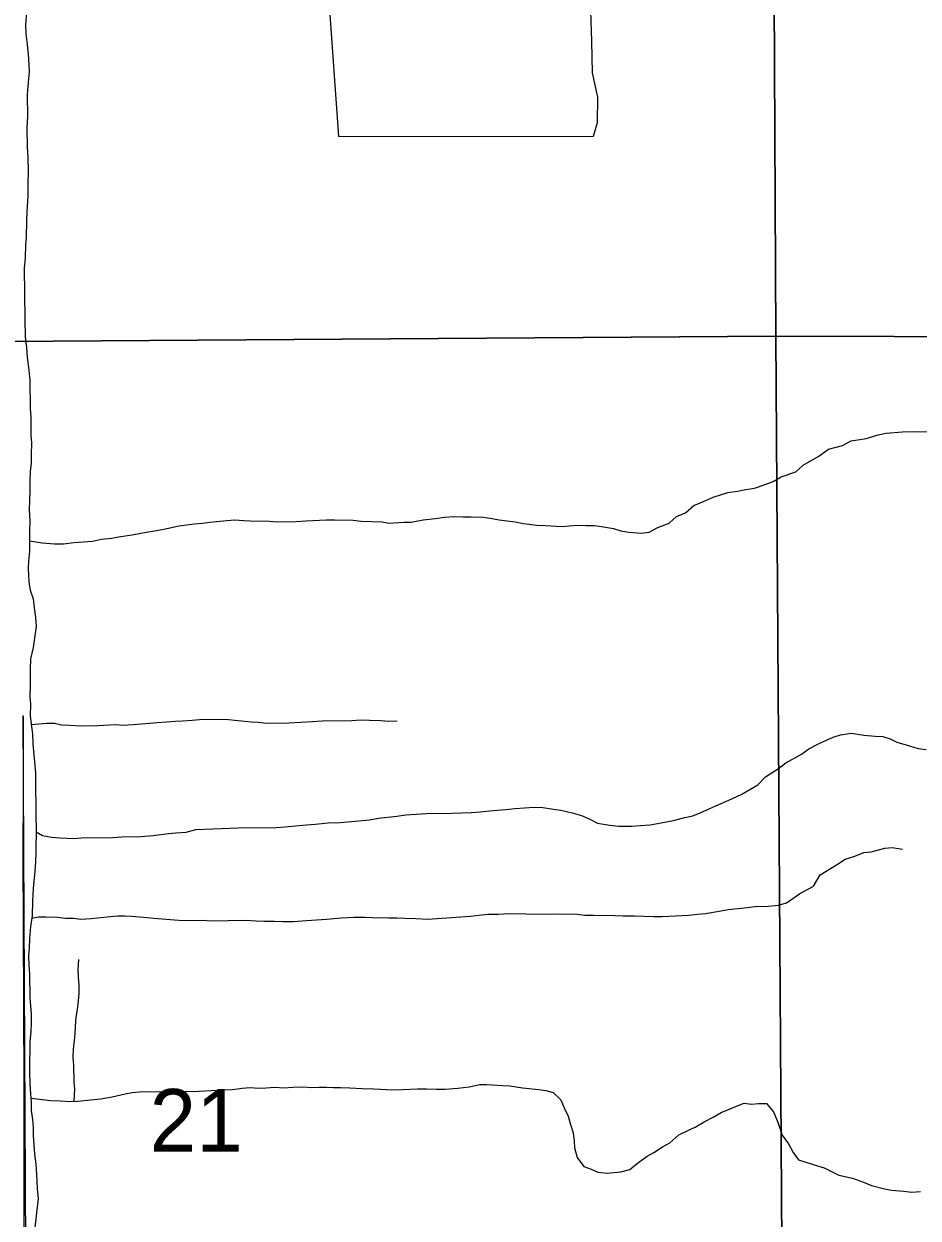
# Model space of a CAD drawing. Extents: x 0 to 34, y 0 to 22.
# Drawn here: x 19.767 to 20.365, y 11.016 to 11.815 of the extents above; entities that cross this region are included whole.
import ezdxf

# ---------------------------------------------------------------- set-up
doc = ezdxf.new("R2010")
doc.units = 0
for name, color, linetype in [('GM_X_Corporation', 7, 'Continuous'), ('GM_X_County_Road', 7, 'Continuous'), ('GM_X_Minor_Lake', 7, 'Continuous'), ('GM_X_Minor_River', 7, 'Continuous'), ('GM_X_Section', 7, 'Continuous'), ('GM_X_Section_Text', 7, 'Continuous')]:
    doc.layers.add(name, color=color, linetype=linetype)

msp = doc.modelspace()

# ---------------------------------------------------------------- linework, layer by layer
at = {"layer": 'GM_X_Corporation'}
msp.add_lwpolyline([(19.26385, 10.07977), (19.77404, 10.1041), (19.77373, 10.13544), (19.77365, 10.17896), (19.7732, 10.26602), (19.77132, 10.47124), (19.77058, 10.53033), (19.7704, 10.56452), (19.77, 10.59281), (19.7662, 11.35213)], dxfattribs=at)
at = {"layer": 'GM_X_County_Road'}
msp.add_lwpolyline([(19.77021, 10.59227), (19.77008, 10.62614), (19.76917, 10.71322), (19.76858, 10.77229), (19.76806, 10.82203), (19.76765, 10.85625), (19.76705, 10.92776), (19.76695, 10.97745), (19.7668, 11.02098), (19.76678, 11.10493), (19.76644, 11.21065), (19.76622, 11.25724), (19.76641, 11.3038), (19.76628, 11.32232), (19.76641, 11.35159)], dxfattribs=at)
at = {"layer": 'GM_X_Minor_Lake'}
for points in [[(19.97712, 11.73997), (20.14794, 11.74011), (20.15053, 11.74923), (20.15079, 11.7663), (20.14727, 11.78258), (20.14674, 11.80343), (20.14622, 11.82391), (20.142, 11.83222), (20.13629, 11.83635), (20.12909, 11.83668), (19.97081, 11.83094)], [(19.97081, 11.83094), (19.97712, 11.73997)]]:
    msp.add_lwpolyline(points, dxfattribs=at)
at = {"layer": 'GM_X_Minor_River'}
for points in [[(19.76846, 11.8231), (19.76781, 11.81474), (19.76789, 11.80866), (19.76874, 11.80145), (19.76958, 11.79501), (19.77005, 11.78818), (19.77012, 11.78324), (19.76945, 11.77601), (19.76879, 11.76803), (19.76899, 11.75322), (19.76871, 11.74562), (19.76887, 11.7327), (19.76934, 11.72587), (19.76946, 11.71637), (19.76919, 11.70801), (19.7693, 11.70004), (19.76867, 11.6894), (19.76837, 11.68369), (19.76813, 11.67229), (19.76782, 11.66735), (19.76755, 11.65861), (19.76688, 11.65176), (19.76732, 11.61758), (19.76748, 11.60543), (19.76833, 11.5986), (19.7688, 11.59177), (19.77005, 11.58343), (19.77052, 11.5766), (19.77076, 11.55761), (19.77121, 11.5523), (19.77137, 11.54015), (19.77183, 11.53445), (19.77154, 11.52685), (19.77162, 11.52116), (19.77093, 11.51545), (19.77063, 11.50937), (19.77071, 11.50291), (19.77042, 11.49645), (19.77013, 11.48961), (19.7706, 11.48278), (19.77031, 11.47518), (19.77048, 11.46226), (19.76981, 11.45542), (19.76949, 11.45048), (19.76999, 11.44174), (19.77082, 11.43606), (19.7728, 11.43038), (19.77363, 11.42432), (19.77448, 11.41787), (19.77494, 11.4118), (19.77284, 11.39772), (19.77104, 11.3901), (19.77075, 11.38288), (19.77088, 11.373), (19.77061, 11.36464), (19.77105, 11.35971), (19.77077, 11.35211), (19.77161, 11.34642), (19.77245, 11.33998), (19.77254, 11.33314), (19.77298, 11.32821), (19.77387, 11.31872), (19.77431, 11.31379)], [(19.77039, 11.4691), (19.77878, 11.46769), (19.78715, 11.46704), (19.79324, 11.46712), (19.80007, 11.46798), (19.81261, 11.4689), (19.81868, 11.47012), (19.82552, 11.47097), (19.83007, 11.47179), (19.83918, 11.47305), (19.84487, 11.47427), (19.85929, 11.47674), (19.86536, 11.47796), (19.87029, 11.47916), (19.88092, 11.48044), (19.88624, 11.4809), (19.89118, 11.48172), (19.90257, 11.48263), (19.90789, 11.48308), (19.9136, 11.48278), (19.91817, 11.48246), (19.93111, 11.48225), (19.93644, 11.48194), (19.94899, 11.48211), (19.95544, 11.48258), (19.96913, 11.48314), (19.97445, 11.48321), (19.98701, 11.483), (19.99234, 11.48231), (20.00642, 11.48173), (20.01099, 11.48103), (20.02088, 11.48155), (20.02582, 11.48161), (20.03379, 11.48324), (20.04214, 11.48411), (20.04822, 11.48495), (20.05468, 11.48541), (20.06077, 11.48512), (20.06609, 11.48519), (20.07408, 11.48491), (20.07865, 11.48421), (20.08475, 11.48315), (20.09542, 11.48178), (20.10114, 11.48072), (20.1099, 11.47969), (20.11561, 11.47939), (20.12703, 11.47878), (20.13159, 11.47922), (20.13729, 11.47968), (20.14299, 11.47937), (20.14832, 11.47944), (20.15327, 11.47875), (20.16128, 11.47733), (20.16624, 11.47588), (20.17158, 11.47481), (20.17996, 11.47416), (20.18527, 11.475), (20.19093, 11.47811), (20.19851, 11.48087), (20.20339, 11.48549), (20.20945, 11.48785), (20.21509, 11.49287), (20.2219, 11.49562), (20.22795, 11.49835), (20.23779, 11.50152), (20.24425, 11.50237), (20.24994, 11.50358), (20.25563, 11.50442), (20.26283, 11.5068), (20.26813, 11.50876), (20.27341, 11.51187), (20.28325, 11.51542), (20.28814, 11.51967), (20.29871, 11.52589), (20.30512, 11.53053), (20.3146, 11.53293), (20.32026, 11.53605), (20.33051, 11.5377), (20.33846, 11.54009), (20.34377, 11.5413), (20.35479, 11.54221), (20.36278, 11.54231), (20.37381, 11.54208)], [(19.77164, 11.34616), (19.78187, 11.34694), (19.78719, 11.34701), (19.79177, 11.34593), (19.79748, 11.34563), (19.80471, 11.34534), (19.81612, 11.34549), (19.82828, 11.34604), (19.83285, 11.34572), (19.83969, 11.34619), (19.85071, 11.34709), (19.85603, 11.34754), (19.86819, 11.34847), (19.87275, 11.34852), (19.87921, 11.34899), (19.88415, 11.34944), (19.90126, 11.34966), (19.91878, 11.348), (19.92335, 11.34768), (19.92906, 11.347), (19.94427, 11.3472), (19.95985, 11.34816), (19.96631, 11.34863), (19.98609, 11.34889), (19.99217, 11.34935), (19.99788, 11.34905), (20.00549, 11.34877), (20.01081, 11.34846), (20.01652, 11.34854)], [(19.77482, 11.27429), (19.77904, 11.27169), (19.78514, 11.27063), (19.79085, 11.27033), (19.79999, 11.26969), (19.8053, 11.27014), (19.82622, 11.27042), (19.8323, 11.27087), (19.84485, 11.27104), (19.85321, 11.27191), (19.86346, 11.27319), (19.86839, 11.27364), (19.87524, 11.27411), (19.88168, 11.27571), (19.89309, 11.27624), (19.90981, 11.27684), (19.93567, 11.27719), (19.94137, 11.27764), (19.95581, 11.27898), (19.96151, 11.27943), (19.97024, 11.28031), (19.97823, 11.28041), (19.98355, 11.28086), (19.99798, 11.2822), (20.00405, 11.28342), (20.01621, 11.28472), (20.02228, 11.28556), (20.02912, 11.28603), (20.03596, 11.2865), (20.05307, 11.28673), (20.066, 11.28728), (20.07208, 11.28774), (20.08081, 11.28862), (20.08917, 11.28911), (20.09525, 11.28995), (20.10817, 11.29088), (20.11388, 11.29058), (20.12112, 11.28953), (20.12607, 11.28884), (20.1337, 11.28704), (20.13981, 11.28522), (20.14555, 11.28264), (20.15053, 11.28005), (20.15892, 11.27864), (20.16463, 11.27795), (20.17338, 11.27807), (20.17946, 11.27853), (20.18591, 11.279), (20.19085, 11.27982), (20.20147, 11.28186), (20.20905, 11.28386), (20.21436, 11.28507), (20.21928, 11.28704), (20.22382, 11.289), (20.22987, 11.29174), (20.24046, 11.29644), (20.24726, 11.29957), (20.25783, 11.30578), (20.26309, 11.31117), (20.27176, 11.3166), (20.27666, 11.32047), (20.28723, 11.32631), (20.29213, 11.32979), (20.29931, 11.33368), (20.30838, 11.3376), (20.31331, 11.33919), (20.32052, 11.34042), (20.3289, 11.33901), (20.33652, 11.33836), (20.34147, 11.33805), (20.34643, 11.33659), (20.35103, 11.33437), (20.35942, 11.33182), (20.36516, 11.33), (20.37049, 11.32931)], [(19.77431, 11.31379), (19.77441, 11.30657), (19.77486, 11.27163), (19.77456, 11.26555), (19.77463, 11.26023), (19.77432, 11.25415), (19.77403, 11.24769), (19.77299, 11.23932), (19.7727, 11.23248), (19.77239, 11.22754), (19.77213, 11.21804), (19.77108, 11.2108), (19.77043, 11.20282), (19.77013, 11.19636), (19.76982, 11.19104), (19.7699, 11.18496), (19.77036, 11.17889), (19.77056, 11.16331), (19.77101, 11.15762), (19.77146, 11.15231), (19.77155, 11.14586), (19.77124, 11.14053), (19.77056, 11.13369), (19.77063, 11.12837), (19.77035, 11.12115), (19.77045, 11.11317), (19.77055, 11.10558), (19.77102, 11.09874), (19.77147, 11.09343), (19.77154, 11.08774), (19.77238, 11.08167), (19.77283, 11.07636), (19.7729, 11.07066), (19.77336, 11.06497), (19.77382, 11.05852), (19.77467, 11.05169), (19.77514, 11.04486), (19.77564, 11.03537), (19.77611, 11.02854), (19.7751, 11.01903), (19.77373, 11.00724)], [(19.77191, 11.21653), (19.77632, 11.21733), (19.78127, 11.2174), (19.78926, 11.21712), (19.79459, 11.21644), (19.79992, 11.21651), (19.80449, 11.21581), (19.81171, 11.21628), (19.82006, 11.21715), (19.82462, 11.21759), (19.82956, 11.21804), (19.83413, 11.2181), (19.83869, 11.21778), (19.84669, 11.21713), (19.85621, 11.21612), (19.8703, 11.21516), (19.87981, 11.21491), (19.88627, 11.215), (19.89198, 11.21469), (19.91518, 11.215), (19.92203, 11.21471), (19.92774, 11.21441), (19.9342, 11.21449), (19.93991, 11.21419), (19.94714, 11.21429), (19.95588, 11.21478), (19.96918, 11.21572), (19.97906, 11.21661), (19.9878, 11.21711), (19.99502, 11.2172), (19.99997, 11.21689), (20.011, 11.21665), (20.01633, 11.21673), (20.02166, 11.21641), (20.02889, 11.21613), (20.03688, 11.21586), (20.05284, 11.21683), (20.06538, 11.21776), (20.07715, 11.21905), (20.084, 11.21914), (20.0916, 11.21962), (20.10263, 11.21939), (20.10872, 11.21909), (20.12203, 11.21927), (20.13725, 11.21909), (20.1422, 11.2184), (20.1479, 11.21847), (20.16236, 11.21829), (20.16769, 11.21798), (20.1753, 11.21808), (20.18824, 11.21749), (20.19394, 11.21757), (20.2118, 11.21856), (20.2175, 11.21902), (20.22282, 11.21947), (20.23193, 11.22111), (20.238, 11.22233), (20.25091, 11.22364), (20.25736, 11.22449), (20.26269, 11.22418), (20.27181, 11.22506), (20.27712, 11.22665), (20.28578, 11.23284), (20.29523, 11.23791), (20.29969, 11.24556), (20.31063, 11.25216), (20.31629, 11.25604), (20.32273, 11.25802), (20.32878, 11.26038), (20.33372, 11.26083), (20.34282, 11.26323), (20.34776, 11.26367), (20.35462, 11.26263)], [(19.80037, 11.09382), (19.80064, 11.10218), (19.8002, 11.10673), (19.80005, 11.11812), (19.79961, 11.12306), (19.79991, 11.12876), (19.8006, 11.13447), (19.80092, 11.13903), (19.80123, 11.14435), (19.80154, 11.15005), (19.80261, 11.15538), (19.8033, 11.16109), (19.80361, 11.16603), (19.80354, 11.17135), (19.80309, 11.17704), (19.80303, 11.18198), (19.80332, 11.18882)], [(19.77125, 11.09594), (19.78477, 11.09437), (19.79086, 11.09407), (19.79733, 11.09378), (19.80265, 11.09385), (19.81138, 11.09472), (19.81822, 11.09558), (19.82581, 11.09682), (19.83453, 11.09883), (19.83909, 11.09965), (19.84403, 11.1001), (19.85734, 11.10027), (19.86533, 11.1), (19.87293, 11.10048), (19.88396, 11.10063), (19.89231, 11.10112), (19.89954, 11.10159), (19.90638, 11.10169), (19.91284, 11.10253), (19.91816, 11.10298), (19.92386, 11.10268), (19.92881, 11.10274), (19.93451, 11.1032), (19.9406, 11.1029), (19.94667, 11.10336), (19.95352, 11.10345), (19.95923, 11.10315), (19.96417, 11.10321), (19.96912, 11.10328), (19.97368, 11.10296), (19.97863, 11.10303), (19.98472, 11.10273), (19.99309, 11.10246), (20.0007, 11.10218), (20.00527, 11.10186), (20.01288, 11.10158), (20.0201, 11.10168), (20.02999, 11.10219), (20.03607, 11.10227), (20.04292, 11.10198), (20.04863, 11.10205), (20.05699, 11.10255), (20.06458, 11.10341), (20.07179, 11.10502), (20.07635, 11.10508), (20.08701, 11.10447), (20.09196, 11.10415), (20.10034, 11.10274), (20.11138, 11.10175), (20.11596, 11.10105), (20.12092, 11.0996), (20.12593, 11.09473), (20.12828, 11.08944), (20.13102, 11.08378), (20.13222, 11.07886), (20.1342, 11.07281), (20.13504, 11.06712), (20.1351, 11.06256), (20.13708, 11.05613), (20.14134, 11.05011), (20.14631, 11.04827), (20.1509, 11.04644), (20.15699, 11.04576), (20.16611, 11.04664), (20.17217, 11.04824), (20.17744, 11.05249), (20.18385, 11.05713), (20.18838, 11.05947), (20.19404, 11.06334), (20.19895, 11.06607), (20.20496, 11.07147), (20.21101, 11.07421), (20.21593, 11.07655), (20.22197, 11.08005), (20.22801, 11.08317), (20.2333, 11.08628), (20.23822, 11.08824), (20.24351, 11.09059), (20.24881, 11.09256), (20.25376, 11.09187), (20.25832, 11.09231), (20.26364, 11.09238), (20.26828, 11.08674), (20.27142, 11.07919), (20.27419, 11.07125), (20.27845, 11.06523), (20.28157, 11.05957), (20.28505, 11.05468), (20.29499, 11.05139), (20.30224, 11.04921), (20.31219, 11.0444), (20.32135, 11.04224), (20.32861, 11.03968), (20.33396, 11.03748), (20.34274, 11.03531), (20.34731, 11.03423), (20.35569, 11.03358), (20.36103, 11.0329), (20.36672, 11.03335)]]:
    msp.add_lwpolyline(points, dxfattribs=at)
at = {"layer": 'GM_X_Section'}
for points in [[(20.26496, 12.60488), (21.31252, 12.61292), (21.31182, 11.93487), (21.29872, 11.60315), (20.27005, 11.60623)], [(19.25603, 12.60125), (20.26496, 12.60488), (20.27005, 11.60623), (19.26987, 11.59924)], [(20.27005, 11.60623), (20.27674, 10.59243), (19.26825, 10.5835), (19.26987, 11.59924)], [(21.29872, 11.60315), (21.30724, 10.59921), (20.49348, 10.60173), (20.27674, 10.59243), (20.27005, 11.60623)]]:
    msp.add_lwpolyline(points, close=True, dxfattribs=at)

# ---------------------------------------------------------------- texts
at = {"layer": 'GM_X_Section_Text'}
msp.add_text('21', height=0.041856, rotation=0.00001, dxfattribs=at).set_placement((19.85081, 11.06015))

doc.saveas('drawing.dxf')
